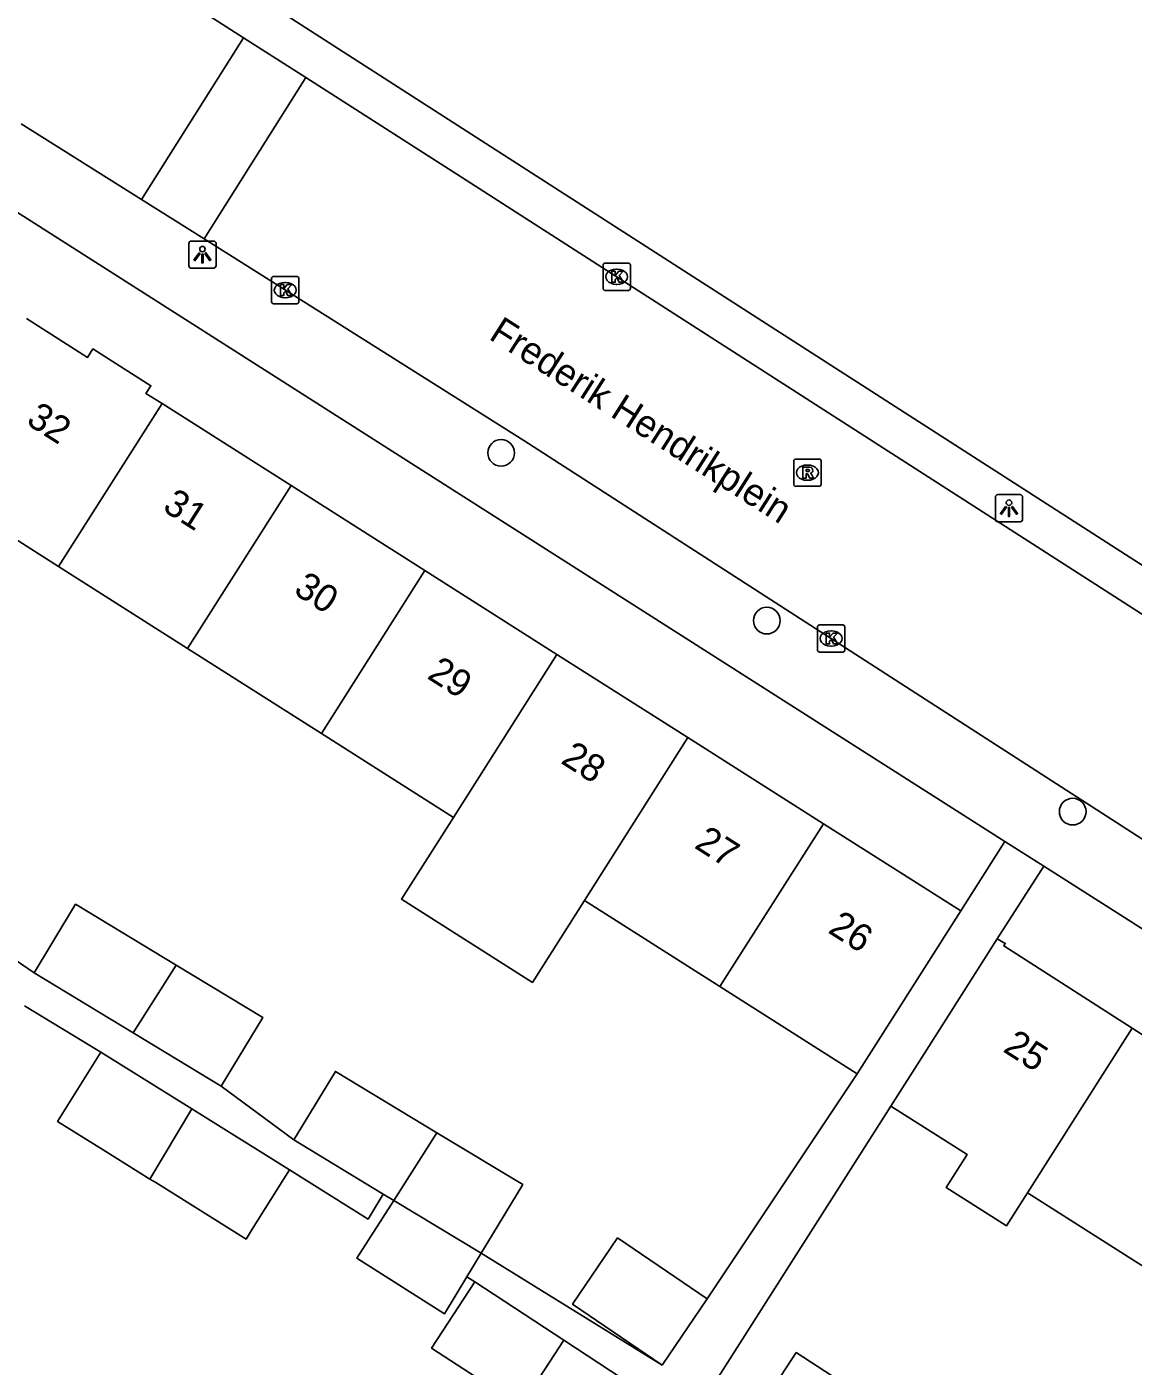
# Model space of a CAD drawing. Extents: x 160107 to 160928, y 382056 to 382918.
# Drawn here: x 160383.94 to 160424.48, y 382277.49 to 382326.59 of the extents above; entities that cross this region are included whole.
import ezdxf

# ---------------------------------------------------------------- set-up
doc = ezdxf.new("R2010")
doc.units = 0
for name, color, linetype in [('IMGEO_Boom', 7, 'Continuous'), ('IMGEO_Kolk', 7, 'Continuous'), ('IMGEO_Lichtpunt', 7, 'Continuous'), ('IMGEO_Openbare_ruimte_label', 7, 'Continuous'), ('IMGEO_Pand', 7, 'Continuous'), ('IMGEO_Pand_nummerreeks', 7, 'Continuous'), ('IMGEO_Rijbaan_lokaal_open', 7, 'Continuous'), ('IMGEO_Rioolput', 7, 'Continuous'), ('IMGEO_Voetpad_open', 7, 'Continuous')]:
    doc.layers.add(name, color=color, linetype=linetype)

msp = doc.modelspace()

# ---------------------------------------------------------------- linework, layer by layer
at = {"layer": 'IMGEO_Boom'}
for centre in [(160401.321, 382310.971), (160411.056, 382304.822), (160422.265, 382297.819)]:
    msp.add_circle(centre, 0.489, dxfattribs=at)
at = {"layer": 'IMGEO_Kolk'}
for p, q in [((160405.056, 382317.003), (160405.056, 382317.855)), ((160405.131, 382317.929), (160405.983, 382317.929)), ((160406.057, 382317.855), (160406.057, 382317.003)), ((160392.91, 382316.514), (160392.91, 382317.366)), ((160392.985, 382317.44), (160393.837, 382317.44)), ((160393.911, 382317.366), (160393.911, 382316.514)), ((160405.544, 382317.709), (160405.569, 382317.709)), ((160393.398, 382317.22), (160393.423, 382317.22)), ((160405.983, 382316.929), (160405.131, 382316.929)), ((160405.567, 382317.149), (160405.542, 382317.149)), ((160393.837, 382316.44), (160392.985, 382316.44)), ((160393.421, 382316.66), (160393.396, 382316.66)), ((160412.913, 382303.74), (160412.913, 382304.592)), ((160412.988, 382304.666), (160413.84, 382304.666)), ((160413.914, 382304.592), (160413.914, 382303.74)), ((160413.401, 382304.446), (160413.426, 382304.446)), ((160413.84, 382303.666), (160412.988, 382303.666)), ((160413.424, 382303.886), (160413.399, 382303.886))]:
    msp.add_line(p, q, dxfattribs=at)
for points in [[(160405.056, 382317.003), (160405.056, 382317.855)], [(160405.131, 382317.929), (160405.983, 382317.929)], [(160406.057, 382317.855), (160406.057, 382317.003)], [(160392.91, 382316.514), (160392.91, 382317.366)], [(160392.985, 382317.44), (160393.837, 382317.44)], [(160393.911, 382317.366), (160393.911, 382316.514)], [(160405.377, 382317.629), (160405.5, 382317.629), (160405.5, 382317.478), (160405.63, 382317.629), (160405.794, 382317.629), (160405.648, 382317.478), (160405.801, 382317.229), (160405.649, 382317.229), (160405.564, 382317.393), (160405.5, 382317.326), (160405.5, 382317.229), (160405.377, 382317.229), (160405.377, 382317.629)], [(160393.231, 382317.14), (160393.354, 382317.14), (160393.354, 382316.989), (160393.484, 382317.14), (160393.648, 382317.14), (160393.502, 382316.989), (160393.655, 382316.74), (160393.503, 382316.74), (160393.418, 382316.904), (160393.354, 382316.837), (160393.354, 382316.74), (160393.231, 382316.74), (160393.231, 382317.14)], [(160405.983, 382316.929), (160405.131, 382316.929)], [(160393.837, 382316.44), (160392.985, 382316.44)], [(160412.913, 382303.74), (160412.913, 382304.592)], [(160412.988, 382304.666), (160413.84, 382304.666)], [(160413.914, 382304.592), (160413.914, 382303.74)], [(160413.234, 382304.366), (160413.357, 382304.366), (160413.357, 382304.215), (160413.487, 382304.366), (160413.651, 382304.366), (160413.505, 382304.215), (160413.658, 382303.966), (160413.506, 382303.966), (160413.421, 382304.13), (160413.357, 382304.063), (160413.357, 382303.966), (160413.234, 382303.966), (160413.234, 382304.366)], [(160413.84, 382303.666), (160412.988, 382303.666)]]:
    msp.add_lwpolyline(points, dxfattribs=at)
for centre, start, end in [((160405.133, 382317.853), 91.552, 178.448), ((160405.133, 382317.853), 91.552, 178.448), ((160405.981, 382317.853), 1.552, 88.448), ((160405.981, 382317.853), 1.552, 88.448), ((160392.987, 382317.364), 91.552, 178.448), ((160392.987, 382317.364), 91.552, 178.448), ((160393.835, 382317.364), 1.552, 88.448), ((160393.835, 382317.364), 1.552, 88.448), ((160405.133, 382317.005), 181.552, 268.448), ((160405.133, 382317.005), 181.552, 268.448), ((160405.981, 382317.005), 271.552, 358.448), ((160405.981, 382317.005), 271.552, 358.448), ((160392.987, 382316.516), 181.552, 268.448), ((160392.987, 382316.516), 181.552, 268.448), ((160393.835, 382316.516), 271.552, 358.448), ((160393.835, 382316.516), 271.552, 358.448), ((160412.99, 382304.59), 91.552, 178.448), ((160412.99, 382304.59), 91.552, 178.448), ((160413.838, 382304.59), 1.552, 88.448), ((160413.838, 382304.59), 1.552, 88.448), ((160412.99, 382303.742), 181.552, 268.448), ((160412.99, 382303.742), 181.552, 268.448), ((160413.838, 382303.742), 271.552, 358.448), ((160413.838, 382303.742), 271.552, 358.448)]:
    msp.add_arc(centre, 0.0765, start, end, dxfattribs=at)
for centre, major_axis, ratio, start_param, end_param in [((160405.543, 382317.429), (-0.387, 0.002), 0.722429, 4.712389, 7.853982), ((160405.568, 382317.429), (-0.39, 0.002), 0.717154, 1.570796, 4.712389), ((160393.397, 382316.94), (-0.387, 0.002), 0.722429, 4.712389, 7.853982), ((160393.422, 382316.94), (-0.39, 0.002), 0.717154, 1.570796, 4.712389), ((160413.4, 382304.166), (-0.387, 0.002), 0.722429, 4.712389, 7.853982), ((160413.425, 382304.166), (-0.39, 0.002), 0.717154, 1.570796, 4.712389)]:
    msp.add_ellipse(centre, major_axis=major_axis, ratio=ratio, start_param=start_param, end_param=end_param, dxfattribs=at)
at = {"layer": 'IMGEO_Lichtpunt'}
for p, q in [((160390.78, 382318.737), (160389.972, 382318.737)), ((160390.78, 382318.737), (160389.972, 382318.737)), ((160389.878, 382318.642), (160389.878, 382317.835)), ((160389.878, 382318.642), (160389.878, 382317.835)), ((160390.874, 382317.835), (160390.874, 382318.642)), ((160390.874, 382317.835), (160390.874, 382318.642)), ((160389.972, 382317.741), (160390.78, 382317.741)), ((160389.972, 382317.741), (160390.78, 382317.741)), ((160420.334, 382309.442), (160419.526, 382309.442)), ((160420.334, 382309.442), (160419.526, 382309.442)), ((160419.432, 382309.347), (160419.432, 382308.54)), ((160419.432, 382309.347), (160419.432, 382308.54)), ((160420.428, 382308.54), (160420.428, 382309.347)), ((160420.428, 382308.54), (160420.428, 382309.347)), ((160419.526, 382308.446), (160420.334, 382308.446)), ((160419.526, 382308.446), (160420.334, 382308.446))]:
    msp.add_line(p, q, dxfattribs=at)
for points in [[(160390.252, 382318.306), (160390.291, 382318.278), (160390.103, 382318.016), (160390.065, 382318.043), (160390.252, 382318.306)], [(160390.354, 382318.258), (160390.401, 382318.258), (160390.401, 382317.936), (160390.354, 382317.936), (160390.354, 382318.258)], [(160390.464, 382318.278), (160390.502, 382318.305), (160390.689, 382318.043), (160390.65, 382318.015), (160390.464, 382318.278)], [(160419.806, 382309.011), (160419.845, 382308.983), (160419.657, 382308.721), (160419.619, 382308.748), (160419.806, 382309.011)], [(160419.908, 382308.963), (160419.955, 382308.963), (160419.955, 382308.641), (160419.908, 382308.641), (160419.908, 382308.963)], [(160420.018, 382308.983), (160420.056, 382309.01), (160420.243, 382308.748), (160420.204, 382308.72), (160420.018, 382308.983)]]:
    msp.add_lwpolyline(points, dxfattribs=at)
for centre in [(160390.377, 382318.44), (160419.931, 382309.145)]:
    msp.add_circle(centre, 0.0994, dxfattribs=at)
for centre, start, end in [((160389.972, 382318.642), 90, 180), ((160389.972, 382318.642), 90, 180), ((160390.78, 382318.642), 0, 90), ((160390.78, 382318.642), 0, 90), ((160389.972, 382317.835), 180, 270), ((160389.972, 382317.835), 180, 270), ((160390.78, 382317.835), 270, 0), ((160390.78, 382317.835), 270, 360), ((160419.526, 382309.347), 90, 180), ((160419.526, 382309.347), 90, 180), ((160420.334, 382309.347), 0, 90), ((160420.334, 382309.347), 0, 90), ((160419.526, 382308.54), 180, 270), ((160419.526, 382308.54), 180, 270), ((160420.334, 382308.54), 270, 0), ((160420.334, 382308.54), 270, 360)]:
    msp.add_arc(centre, 0.0946, start, end, dxfattribs=at)
at = {"layer": 'IMGEO_Pand'}
for points in [[(160383.927, 382315.896), (160386.169, 382314.471), (160386.366, 382314.781), (160388.486, 382313.433), (160388.307, 382313.152), (160388.895, 382312.778)], [(160388.895, 382312.778), (160385.101, 382306.807)], [(160388.895, 382312.778), (160393.622, 382309.774)], [(160385.101, 382306.807), (160380.151, 382309.953)], [(160389.827, 382303.803), (160393.622, 382309.774)], [(160393.622, 382309.774), (160398.528, 382306.656)], [(160389.827, 382303.803), (160385.101, 382306.807)], [(160398.528, 382306.656), (160394.734, 382300.685)], [(160398.528, 382306.656), (160403.368, 382303.58)], [(160394.734, 382300.685), (160389.827, 382303.803)], [(160399.574, 382297.609), (160403.368, 382303.58)], [(160403.368, 382303.58), (160408.166, 382300.531)], [(160399.574, 382297.609), (160394.734, 382300.685)], [(160408.166, 382300.531), (160404.372, 382294.56)], [(160408.166, 382300.531), (160413.128, 382297.377)], [(160404.372, 382294.56), (160402.466, 382291.561), (160397.668, 382294.61), (160399.574, 382297.609)], [(160413.128, 382297.377), (160409.334, 382291.406)], [(160413.128, 382297.377), (160418.16, 382294.179)], [(160384.206, 382291.908), (160385.728, 382294.422), (160389.415, 382292.19)], [(160409.334, 382291.406), (160404.372, 382294.56)], [(160418.16, 382294.179), (160415.479, 382289.959), (160414.366, 382288.208)], [(160415.602, 382287.025), (160416.817, 382288.936), (160419.498, 382293.155)], [(160424.444, 382289.881), (160419.739, 382292.897), (160419.791, 382292.99), (160419.498, 382293.155)], [(160387.838, 382289.71), (160384.206, 382291.908)], [(160387.838, 382289.71), (160389.415, 382292.19)], [(160389.415, 382292.19), (160392.59, 382290.269), (160391.068, 382287.755)], [(160414.366, 382288.208), (160409.334, 382291.406)], [(160420.606, 382283.845), (160424.444, 382289.881)], [(160429.163, 382286.856), (160424.444, 382289.881)], [(160391.068, 382287.755), (160387.838, 382289.71)], [(160386.658, 382289.004), (160385.07, 382286.465), (160386.736, 382285.423), (160388.449, 382284.351)], [(160386.658, 382289.004), (160389.99, 382286.92)], [(160393.727, 382285.783), (160395.249, 382288.297), (160398.964, 382286.048)], [(160388.449, 382284.351), (160389.99, 382286.92)], [(160389.99, 382286.92), (160393.564, 382284.683)], [(160420.606, 382283.845), (160419.838, 382282.636), (160417.633, 382284.037), (160418.402, 382285.246), (160415.602, 382287.025)], [(160398.964, 382286.048), (160397.387, 382283.568)], [(160398.964, 382286.048), (160402.111, 382284.144), (160400.589, 382281.63)], [(160397.001, 382283.801), (160393.727, 382285.783)], [(160393.564, 382284.683), (160392.202, 382282.507), (160391.976, 382282.146), (160388.664, 382284.217), (160388.449, 382284.351)], [(160397.387, 382283.568), (160396.036, 382281.443), (160399.241, 382279.404), (160400.066, 382280.766)], [(160397.387, 382283.568), (160397.001, 382283.801)], [(160400.589, 382281.63), (160397.387, 382283.568)], [(160425.338, 382280.837), (160420.606, 382283.845)], [(160407.22, 382277.527), (160403.933, 382279.767), (160405.586, 382282.193), (160408.873, 382279.954)], [(160400.589, 382281.63), (160400.066, 382280.766)], [(160403.624, 382278.446), (160402.043, 382276.022), (160398.775, 382278.153), (160400.355, 382280.577)], [(160400.355, 382280.577), (160403.624, 382278.446)], [(160408.873, 382279.954), (160407.22, 382277.527)], [(160410.617, 382275.665), (160412.133, 382277.988), (160415.49, 382275.799)]]:
    msp.add_lwpolyline(points, dxfattribs=at)
at = {"layer": 'IMGEO_Rijbaan_lokaal_open'}
for points in [[(160391.886, 382326.191), (160382.828, 382331.994), (160381.398, 382332.855)], [(160388.146, 382320.258), (160391.886, 382326.191)], [(160391.886, 382326.191), (160394.166, 382324.73)], [(160390.438, 382318.814), (160394.166, 382324.73)], [(160394.166, 382324.73), (160399.869, 382321.076), (160436.26, 382297.701)], [(160383.739, 382323.036), (160388.146, 382320.258)], [(160388.146, 382320.258), (160390.438, 382318.814)], [(160390.438, 382318.814), (160402.157, 382311.428), (160432.528, 382291.84)]]:
    msp.add_lwpolyline(points, dxfattribs=at)
at = {"layer": 'IMGEO_Rioolput'}
for p, q in [((160412.043, 382309.819), (160412.043, 382310.671)), ((160412.118, 382310.745), (160412.97, 382310.745)), ((160412.531, 382310.525), (160412.556, 382310.525)), ((160413.044, 382310.671), (160413.044, 382309.819)), ((160412.554, 382309.965), (160412.529, 382309.965)), ((160412.97, 382309.745), (160412.118, 382309.745))]:
    msp.add_line(p, q, dxfattribs=at)
for points in [[(160412.043, 382309.819), (160412.043, 382310.671)], [(160412.118, 382310.745), (160412.97, 382310.745)], [(160412.632, 382310.443), (160412.38, 382310.445), (160412.38, 382310.045)], [(160413.044, 382310.671), (160413.044, 382309.819)], [(160412.38, 382310.045), (160412.504, 382310.045), (160412.504, 382310.207), (160412.515, 382310.207)], [(160412.558, 382310.364), (160412.504, 382310.364), (160412.504, 382310.283)], [(160412.504, 382310.283), (160412.556, 382310.283)], [(160412.562, 382310.178), (160412.633, 382310.045), (160412.773, 382310.045), (160412.708, 382310.171)], [(160412.97, 382309.745), (160412.118, 382309.745)]]:
    msp.add_lwpolyline(points, dxfattribs=at)
for centre, radius, start, end in [((160412.12, 382310.669), 0.0765, 91.552, 178.448), ((160412.12, 382310.669), 0.0765, 91.552, 178.448), ((160412.631, 382310.333), 0.109, 350.3612, 89.416), ((160412.968, 382310.669), 0.0765, 1.552, 88.448), ((160412.968, 382310.669), 0.0765, 1.552, 88.448), ((160412.514, 382310.154), 0.0533, 26.0293, 88.6989), ((160412.54, 382310.472), 0.19, 274.7715, 282.9687), ((160412.564, 382310.268), 0.0964, 77.0061, 93.1865), ((160412.578, 382310.325), 0.0378, 276.6634, 79.6772), ((160412.629, 382310.333), 0.112, 277.5842, 350.9817), ((160412.613, 382310.118), 0.108, 29.5134, 73.7905), ((160412.12, 382309.821), 0.0765, 181.552, 268.448), ((160412.12, 382309.821), 0.0765, 181.552, 268.448), ((160412.968, 382309.821), 0.0765, 271.552, 358.448), ((160412.968, 382309.821), 0.0765, 271.552, 358.448)]:
    msp.add_arc(centre, radius, start, end, dxfattribs=at)
for centre, major_axis, ratio, start_param, end_param in [((160412.53, 382310.245), (-0.387, 0.002), 0.722429, 4.712389, 7.853982), ((160412.555, 382310.245), (-0.39, 0.002), 0.717154, 1.570796, 4.712389)]:
    msp.add_ellipse(centre, major_axis=major_axis, ratio=ratio, start_param=start_param, end_param=end_param, dxfattribs=at)
at = {"layer": 'IMGEO_Voetpad_open'}
for points in [[(160425.707, 382306.276), (160387.099, 382331.11)], [(160419.783, 382296.727), (160380.656, 382321.65)], [(160419.783, 382296.727), (160418.16, 382294.179)], [(160421.207, 382295.82), (160419.783, 382296.727)], [(160419.498, 382293.155), (160421.207, 382295.82)], [(160447.959, 382278.78), (160421.207, 382295.82)], [(160384.206, 382291.908), (160381.178, 382293.969)], [(160383.854, 382290.698), (160386.658, 382289.004)], [(160414.366, 382288.208), (160408.873, 382279.954)], [(160393.727, 382285.783), (160391.068, 382287.755)], [(160415.602, 382287.025), (160409.035, 382276.697), (160410.617, 382275.665)], [(160393.564, 382284.683), (160396.444, 382282.88), (160397.001, 382283.801)], [(160407.22, 382277.527), (160400.589, 382281.63)], [(160400.066, 382280.766), (160400.355, 382280.577)], [(160403.624, 382278.446), (160406.18, 382276.755)]]:
    msp.add_lwpolyline(points, dxfattribs=at)

# ---------------------------------------------------------------- texts
at = {"layer": 'IMGEO_Openbare_ruimte_label'}
msp.add_text('Frederik Hendrikplein', height=1, rotation=327.5024, dxfattribs=at).set_placement((160400.831, 382315.169))
at = {"layer": 'IMGEO_Pand_nummerreeks'}
for s, rotation, p in [('32', 327.6032, (160383.877, 382312.049)), ('31', 327.6032, (160388.871, 382308.88)), ('30', 327.6032, (160393.674, 382305.832)), ('29', 327.6032, (160398.568, 382302.726)), ('28', 327.6032, (160403.467, 382299.619)), ('27', 327.6032, (160408.361, 382296.513)), ('26', 327.6032, (160413.257, 382293.406)), ('25', 327.3518, (160419.67, 382289.046))]:
    msp.add_text(s, height=1, rotation=rotation, dxfattribs=at).set_placement(p)

doc.saveas('drawing.dxf')
